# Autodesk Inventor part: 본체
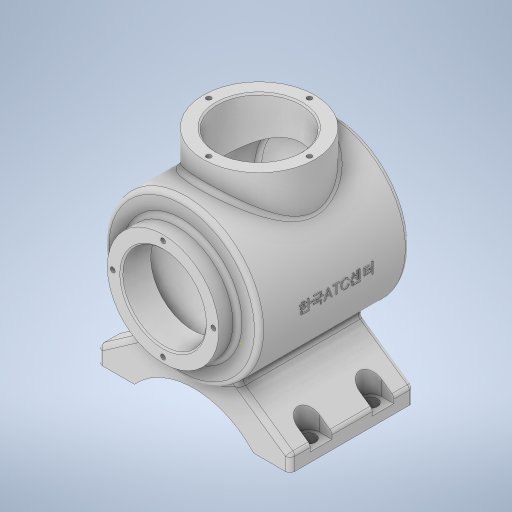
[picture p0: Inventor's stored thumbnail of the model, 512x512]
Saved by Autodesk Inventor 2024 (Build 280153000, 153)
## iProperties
Created: 2023-08
Part Number: 본체
Material: 일반
Document SubType Name: Modeling
Designer: Owner
Density: 1 g/cm^3
Appearance: 기본값
Mass: 480.277 g
Surface Area: 1060.33 cm^2
Volume: 480.277 cm^3
Author: Owner
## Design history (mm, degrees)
sketch "스케치1"
  geometry: L1 (0, 0)-(120, 0); L2 (0, 36)-(12, 36); L3 (12, 36)-(12, 50); L4 (12, 50)-(108.336, 50); L5 (103.887, 43)-(19, 43); L6 (19, 43)-(19, 27); L7 (19, 27)-(0, 27); L8 (0, 27)-(0, 36); A1 r 113 centre (7, 0) between (120, 0) and (108.336, 50); A2 r 106 centre (7, 0) between (113, 0) and (103.887, 43)
  constraints: 16 end point, 5 perpendicular, 4 point on circle, 3 horizontal, 2 centre point, 2 point on line, 1 concentric, 1 vertical alignment
  dimensions: "d20" = 120 distance of L1.start L1.end; "d21" = 113 radius of A1; "d22" = 7 radial gap between concentric circles of A1 A2; "d23" = 54 diameter of L7 L1; "d24" = 72 diameter of L2 L1; "d25" = 86 diameter of L5 L1; "d26" = 100 diameter of L4 L1; "d27" = 19 distance of L6.end L7.end; "d28" = 108 distance from line of L1.end L3
revolve "회전1" sketch "스케치1" stored, may be unused: angle "d29" = 90 deg
fillet "모깎기1" dims "d30" = 3
node "작업 평면1"
sketch "스케치2"
  geometry: L1 (0, 36)-(0, -36) reference; C1 r 36 at (-62, 0); 2 further points
  constraints: 1 centre point, 1 horizontal alignment, 1 midpoint
  dimensions: "d32" = 72 diameter of C1; "d33" = 62 distance from line of L1 C1.centre
extrude "돌출1" join sketch "스케치2" stored distance "d34" = 10; taper "d35" = 0 deg
sketch "스케치3"
  geometry: C1 r 36 at (0, 0) reference; 2 further points
  constraints: 1 coincident
hole "구멍1" sketch "스케치3" at (0, 0) diameter "d36" = 54; stored, may be unused: countersink angle "d40" = 90 deg, drill point angle "d42" = 0 deg; dims "d37" = 6, "d38" = 8, "d39" = 4.4, "d41" = 67
node "작업 평면2"
sketch "스케치4"
  geometry: L1 (-26.694, -42.278)-(-62, -67); L2 (-62, -67)-(-62, -77); L3 (-62, -77)-(-38.5, -77); L4 (38.5, -77)-(62, -77); L5 (62, -77)-(62, -67); L6 (62, -67)-(26.694, -42.278); A1 r 50 centre (0, 0) between (-26.694, -42.278) and (26.694, -42.278) reference; A2 r 52.096 centre (0, -112.096) between (38.5, -77) and (-38.5, -77); 2 further points
  constraints: 12 end point, 5 point on circle, 3 equal length, 2 perpendicular, 1 centre point, 1 horizontal, 1 horizontal alignment, 1 vertical
  dimensions: "d44" = 55 deg angle of L6 L5; "d45" = 55 deg angle of L2 L1; "d46" = 124 distance between parallel lines of L5 L2; "d47" = 10 distance of L4.end L5.end; "d48" = 77 distance from line of L3 point (0, 0); "d49" = 77 distance of L4.start L3.end; "d50" = 17 distance from line of point (0, -60) L4
extrude "돌출2" join sketch "스케치4" distance "d51" = 80; taper "d52" = 0 deg
node "작업 평면3"
sketch "스케치5"
  geometry: L1 (60, 15.5)-(60, 39.438); L2 (67, 15.5)-(67, 23.5); L3 (53, 23.5)-(53, 15.5); L4 (0, 23.5)-(80, 23.5) reference; L5 (80, 23.5)-(80, 0) reference; A1 r 7 centre (60, 15.5) between (53, 15.5) and (67, 15.5); 2 further points
  constraints: 8 end point, 2 point on circle, 2 point on line, 2 tangent, 2 vertical, 1 centre point, 1 midpoint, 1 parallel
  dimensions: "d54" = 14 distance between parallel lines of L3 L2; "d55" = 20 distance between parallel lines of L1 L5; "d56" = 8 distance from line of L4 L1.start
extrude "돌출3" cut sketch "스케치5" distance "d57" = 26.25; taper "d58" = 0 deg
sketch "스케치6"
  geometry: C1 r 4.5 at (60, -15.5); A1 r 7 centre (60, -15.5) between (67, -15.5) and (53, -15.5) reference; 1 further point
  constraints: 1 centre point, 1 concentric
  dimensions: "d59" = 9 diameter of C1
extrude "돌출4" cut sketch "스케치6" extent not by distance; stored distance "d60" = 0; taper "d61" = 0 deg
fillet "모깎기2" dims "d65" = 3
fillet "모깎기3" dims "d66" = 3
fillet "모깎기4" dims "d67" = 3
fillet "모깎기5" dims "d68" = 3
chamfer "모따기1" distance "d69" = 1; stored, may be unused: second distance "d70" = 2, angle "d71" = 45 deg
sketch "스케치7" dims "d72" = 65
  geometry: 3 further points
  constraints: 2 vertical alignment, 1 coincident, 2 other
hole "구멍2" sketch "스케치7" at (0, 32.5) diameter "d73" = 3.242; stored, may be unused: countersink angle "d77" = 90 deg, drill point angle "d79" = 0 deg; dims "d74" = 8, "d75" = 4, "d76" = 2, "d78" = 10
sketch "스케치8" dims "d83" = 65
  geometry: C1 r 36 at (0, 0) reference; 3 further points
  constraints: 2 vertical alignment, 1 coincident, 2 other
hole "구멍3" sketch "스케치8" at (0, 32.5) diameter "d84" = 3.242; stored, may be unused: countersink angle "d88" = 90 deg, drill point angle "d90" = 0 deg; dims "d85" = 8, "d86" = 4, "d87" = 2, "d89" = 10
node "작업 평면4"
sketch "스케치9"
  geometry: 1 further point
sketch "스케치10"
  geometry: L1 (-60.168, -36)-(-60.168, 36) reference; 2 further points
  constraints: 1 horizontal alignment, 1 other
  dimensions: "d94" = 62 distance from line of point (1.832, 0) L1
feature "엠보싱1" sketch "스케치10" dims "d95" = 0.5, "d96" = 0
feature "ɉ耀ɋ耀ɍ耀ɏ耀ɑ耀ɓ耀ɕ耀ɗ耀" dims "d20" = 120, "d21" = 113, "d22" = 7, "d23" = 54, "d24" = 72, "d25" = 86, "d26" = 100, "d27" = 19, "d28" = 108, "d29" = 90 deg, "d30" = 3, "d31" = 65, "d32" = 72, "d33" = 62, "d34" = 10, "d35" = 0, "d36" = 54, "d37" = 6, "d38" = 8, "d39" = 4.4, "d40" = 90 deg, "d41" = 67, "d42" = 0, "d43" = -20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
node "솔리드1"
pattern_linear "직사각형 패턴1" dims "d64" = 40
mirror "미러1"
pattern_circular "원형 패턴1" dims angle "d81" = 360 deg
pattern_circular "원형 패턴2" dims angle "d92" = 360 deg
feature "A9D066F2-1C7D-4E18-AEED-F7BC21143FA4" dims "d36" = 54, "d37" = 6, "d38" = 8, "d39" = 4.4, "d40" = 90 deg, "d41" = 67, "d42" = 0
